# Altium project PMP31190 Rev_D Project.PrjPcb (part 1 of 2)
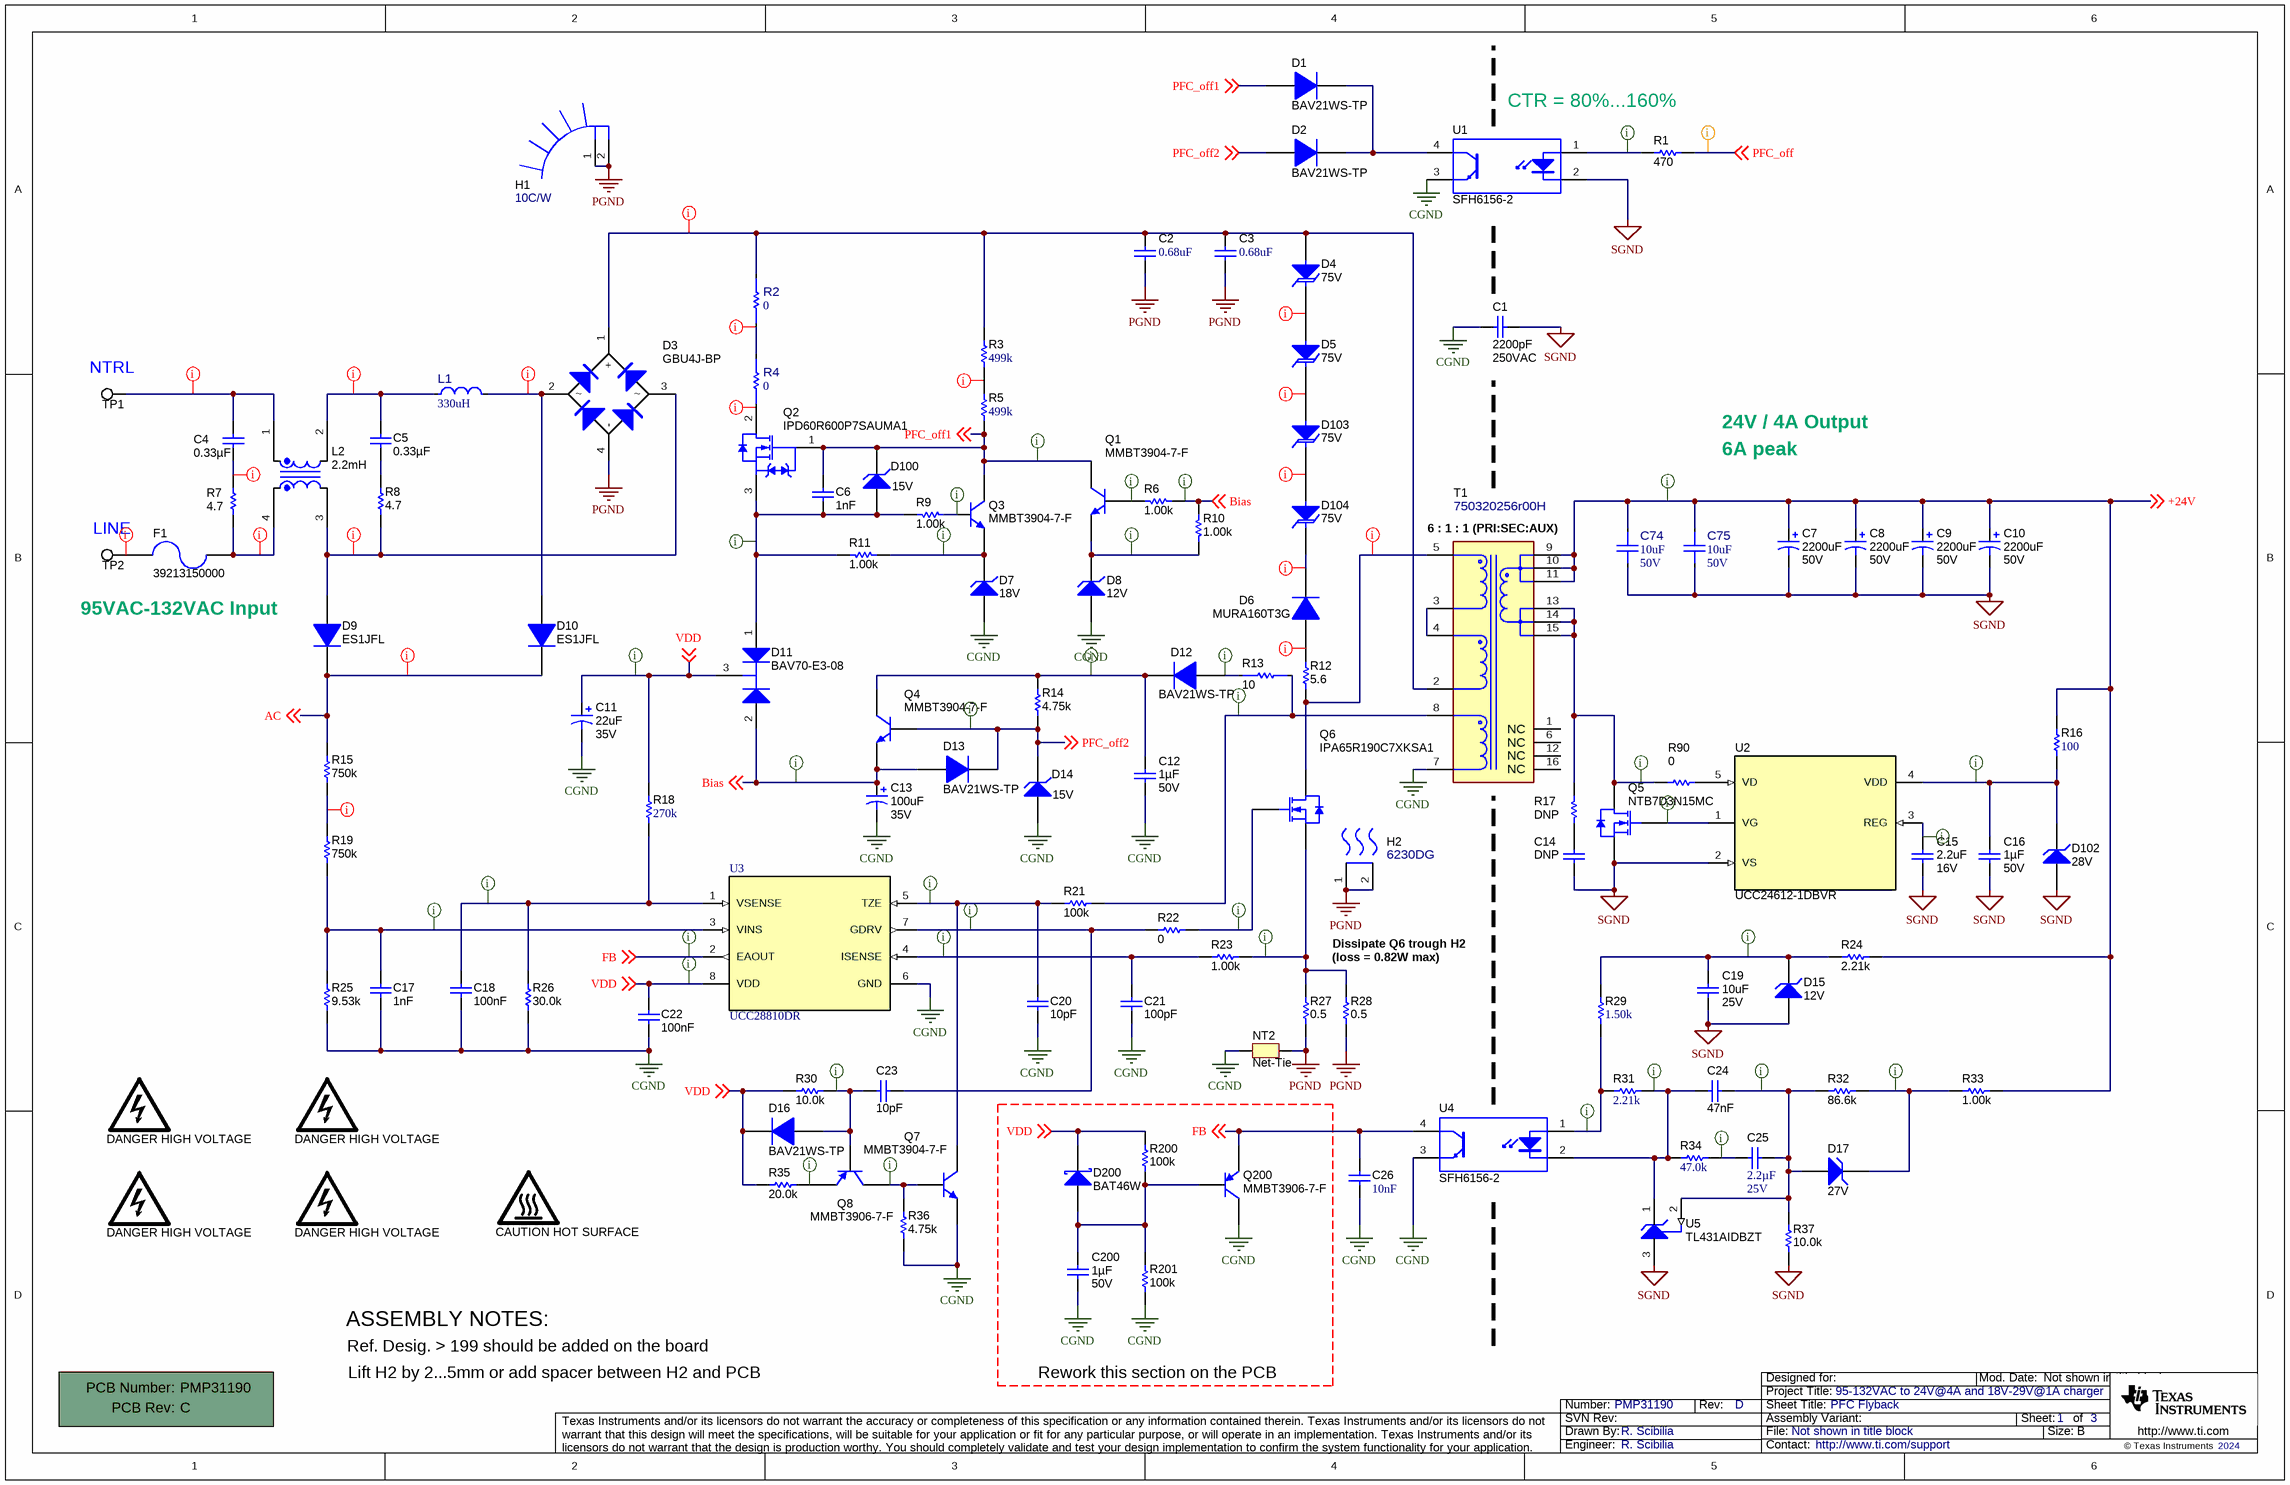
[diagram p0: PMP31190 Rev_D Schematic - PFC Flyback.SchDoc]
CopyrightYear: 2024; PCB_Layout: R Scibilia; PCB_Rev: C; PRJ_Engineer: R. Scibilia; PRJ_Number: PMP31190; PRJ_Title: 95-132VAC to 24V@4A and 18V-29V@1A charger; SCH_Rev: D; TechSupport: http://www.ti.com/support
3 sheets, 254 parts. Net scope: global (net labels, ports and power ports of the same name join across sheets).
Board file: PMP31190 Rev_C Board.PcbDoc
Sheets:
  PMP31190 Rev_D Schematic - PFC Flyback.SchDoc
  PMP31190 Rev_D Schematic - Charger.SchDoc
  PMP31190 Rev_D Schematic - LaunchPad Interface.SchDoc

## Sheet PMP31190 Rev_D Schematic - PFC Flyback.SchDoc: PFC Flyback
size 431 x 279 mm; Date: Not shown in title block; ApprovedBy: Not shown in title block; CheckedBy: Not shown in title block; Author: Not shown in title block; CompanyName: Not shown in title block; DrawnBy: R. Scibilia; Engineer: Not shown in title block; Organization: Not shown in title block; Address1: Not shown in title block; Address2: Not shown in title block; Address3: Not shown in title block; Address4: Not shown in title block; DocumentNumber: 1; Revision: Use project parameter SCH_Rev; SheetNumber: 1; SheetTotal: 3; PageSetup: Record=PageOptions¦CenterHorizontal=True¦CenterVertical=True¦PrintScale=1.00¦XCorrection=1.00¦YCorrection=1.00¦PrintKind=0¦BorderSize=5000000¦LeftOffset=0¦BottomOffset=0¦Orientation=2¦PaperLength=1000¦PaperWidth=1000¦Scale=100¦PaperSource=15¦PrintQuality=600¦MediaType=1¦DitherType=10¦PaperKind=Letter¦PrintScaleMode=1

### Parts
!PCB1  Printed Circuit Board  (value not drawn)  (mechanical)
C1  ValueDisplayed: 2200pF  VDC_V: 250VAC  [DE1_600x400x900]  (hidden comment: DE1E3RA222MA4BN01F)
C2  ValueDisplayed: 0.68uF  [B32923_16.5mm_10.5]  (hidden comment: B32923C3684M000)
C3  ValueDisplayed: 0.68uF  [B32923_16.5mm_10.5]  (hidden comment: B32923C3684M000)
C4  ValueDisplayed: 0.33µF  [WCAP-FTX2_1500x850]  (hidden comment: 890334024003)
C5  ValueDisplayed: 0.33µF  [WCAP-FTX2_1500x850]  (hidden comment: 890334024003)
C6  Cap_F: 1nF  [0603]  (hidden comment: 885012206083)
C7  VDC_V: 50V  ValueDisplayed: 2200uF  [CAPPR7.5-18x31.5]  (hidden comment: 50YXS2200MEFC18X31.5)
C8  VDC_V: 50V  ValueDisplayed: 2200uF  [CAPPR7.5-18x31.5]  (hidden comment: 50YXS2200MEFC18X31.5)
C9  VDC_V: 50V  ValueDisplayed: 2200uF  [CAPPR7.5-18x31.5]  (hidden comment: 50YXS2200MEFC18X31.5)
C10  VDC_V: 50V  ValueDisplayed: 2200uF  [CAPPR7.5-18x31.5]  (hidden comment: 50YXS2200MEFC18X31.5)
C11  VDC_V: 35V  ValueDisplayed: 22uF  [CAPSMT_62_E55]  (hidden comment: 865080542006)
C12  Cap_F: 1µF  VDC_V: 50V  [0805_HV]  (hidden comment: 885012207103)
C13  VDC_V: 35V  ValueDisplayed: 100uF  [CAPSMT_62_F80]  (hidden comment: EEE-FK1V101XP)
C14  DNP  [0805_HV]
C15  VDC_V: 16V  ValueDisplayed: 2.2uF  [0603]  (hidden comment: 885012106018)
C16  Cap_F: 1µF  VDC_V: 50V  [0805_HV]  (hidden comment: 885012207103)
C17  Cap_F: 1nF  [0603]  (hidden comment: 885012206083)
C18  Cap_F: 100nF  [0603]  (hidden comment: 885012206095)
C19  VDC_V: 25V  ValueDisplayed: 10uF  [1206_180]  (hidden comment: 885012108021)
C20  ValueDisplayed: 10pF  [0603]  (hidden comment: 885012006051)
C21  ValueDisplayed: 100pF  [0603]  (hidden comment: 885012006057)
C22  Cap_F: 100nF  [0603]  (hidden comment: 885012206095)
C23  ValueDisplayed: 10pF  [0603]  (hidden comment: 885012006051)
C24  Cap_F: 47nF  [0603]  (hidden comment: 885012206093)
C25  Cap_F: 2.2µF  VDC_V: 25V  [0805_HV]  (hidden comment: CGA4J3X7R1E225K125AB)
C26  Cap_F: 10nF  [0603]  (hidden comment: 885012206089)
C74  ValueDisplayed: 10uF  VDC_V: 50V  [FP-C3225X7R1H106K250AC_1210-MFG]  (hidden comment: C3225X7R1H106K250AC)
C75  ValueDisplayed: 10uF  VDC_V: 50V  [FP-C3225X7R1H106K250AC_1210-MFG]  (hidden comment: C3225X7R1H106K250AC)
C200  Cap_F: 1µF  VDC_V: 50V  [0805_HV]  (hidden comment: 885012207103)
D1  BAV21WS-TP  [SOD-323]
D2  BAV21WS-TP  [SOD-323]
D3  GBU4J-BP  [GBU]
D4  value 75V  [SMC]  (hidden comment: SMCJ75A)
D5  value 75V  [SMC]  (hidden comment: SMCJ75A)
D6  MURA160T3G  [SMA]
D7  value 18V  [SOD-323]  (hidden comment: MMSZ5248BS-7-F)
D8  value 12V  [SOD-323]  (hidden comment: MMSZ5242BS-7-F)
D9  ES1JFL  [MINI-SMA]
D10  ES1JFL  [MINI-SMA]
D11  BAV70-E3-08  [SOT-23L]
D12  BAV21WS-TP  [SOD-323]
D13  BAV21WS-TP  [SOD-323]
D14  value 15V  [SOD-323]  (hidden comment: MMSZ5245BS-7-F)
D15  value 12V  [SOD-323]  (hidden comment: MMSZ5242BS-7-F)
D16  BAV21WS-TP  [SOD-323]
D17  value 27V  [SOD-323]  (hidden comment: MMSZ5254BS-7-F)
D100  value 15V  [SOD-323]  (hidden comment: MMSZ5245BS-7-F)
D102  value 28V  [SOD-323]  (hidden comment: MMSZ5255BS-7-F)
D103  value 75V  [SMC]  (hidden comment: SMCJ75A)
D104  value 75V  [SMC]  (hidden comment: SMCJ75A)
D200  BAT46W  [SOD-323F]
F1  39213150000  [FUSE_392]
H1  value 10C/W  [HSINK_V6560W]  (hidden comment: V6560W)
H2  6230DG  [FP-6230DG_PTH_HTSNK-MFG]
L1  value 330uH  [FP-7447010_RADIAL-MFG]  (hidden comment: 7447060)
L2  value 2.2mH  [WE-CMB_Type_S]  (hidden comment: 744822222)
LOGO1  DANGER HIGH VOLTAGE  [IEC_HighVoltage_Small]  (no BOM)
LOGO2  DANGER HIGH VOLTAGE  [IEC_HighVoltage_Small]  (no BOM)
LOGO3  DANGER HIGH VOLTAGE  [IEC_HighVoltage_Small]  (no BOM)
LOGO4  DANGER HIGH VOLTAGE  [IEC_HighVoltage_Small]  (no BOM)
Logo5  CAUTION HOT SURFACE  [IEC_HotSurface_Small]  (no BOM)
NT2  Net-Tie  [Net-Tie_50milWide_30milLong]  (net tie, no BOM)
Q1  MMBT3904-7-F  [SOT-23]
Q2  IPD60R600P7SAUMA1  [DPAK]
Q3  MMBT3904-7-F  [SOT-23]
Q4  MMBT3904-7-F  [SOT-23]
Q5  NTB7D3N15MC  [DDPAK]
Q6  IPA65R190C7XKSA1  [TO-220FP]
Q7  MMBT3904-7-F  [SOT-23]
Q8  MMBT3906-7-F  [SOT-23]
Q200  MMBT3906-7-F  [SOT-23]
R1  ValueDisplayed: 470  [0603]  (hidden comment: RC0603FR-07470RL)
R2  value 0  [FP-RMCF1206ZT0R00_1206-MFG]  (hidden comment: RMCF1206ZT0R00)
R3  ValueDisplayed: 499k  [1206]  (hidden comment: RC1206FR-07499KL)
R4  value 0  [FP-RMCF1206ZT0R00_1206-MFG]  (hidden comment: RMCF1206ZT0R00)
R5  ValueDisplayed: 499k  [1206]  (hidden comment: RC1206FR-07499KL)
R6  ValueDisplayed: 1.00k  [0603]  (hidden comment: RC0603FR-071KL)
R7  ValueDisplayed: 4.7  [2010]  (hidden comment: CRM2010-JW-4R7ELF)
R8  ValueDisplayed: 4.7  [2010]  (hidden comment: CRM2010-JW-4R7ELF)
R9  ValueDisplayed: 1.00k  [0603]  (hidden comment: RC0603FR-071KL)
R10  ValueDisplayed: 1.00k  [0603]  (hidden comment: RC0603FR-071KL)
R11  ValueDisplayed: 1.00k  [0603]  (hidden comment: RC0603FR-071KL)
R12  ValueDisplayed: 5.6  [2512]  (hidden comment: CRCW25125R60JNEG)
R13  Res_ohm: 10  [FP-560050316012_0603-MFG]  (hidden comment: 560050316012)
R14  ValueDisplayed: 4.75k  [0603]  (hidden comment: RC0603FR-074K75L)
R15  ValueDisplayed: 750k  [1206]  (hidden comment: RC1206FR-07750KL)
R16  ValueDisplayed: 100  [0603]  (hidden comment: ESR03EZPJ101)
R17  DNP  [1206]
R18  ValueDisplayed: 270k  [0603]  (hidden comment: RC0603FR-07270KL)
R19  ValueDisplayed: 750k  [1206]  (hidden comment: RC1206FR-07750KL)
R21  ValueDisplayed: 100k  [0603]  (hidden comment: CRCW0603100KDHEAP)
R22  ValueDisplayed: 0  [0603]  (hidden comment: RMCF0603ZT0R00)
R23  ValueDisplayed: 1.00k  [0603]  (hidden comment: RC0603FR-071KL)
R24  ValueDisplayed: 2.21k  [0805_HV]  (hidden comment: ERJ-6ENF2211V)
R25  ValueDisplayed: 9.53k  [0603]  (hidden comment: RC0603FR-079K53L)
R26  ValueDisplayed: 30.0k  [0603]  (hidden comment: ERJ-3EKF3002V)
R27  ValueDisplayed: 0.5  [2512]  (hidden comment: 560050363011)
R28  ValueDisplayed: 0.5  [2512]  (hidden comment: 560050363011)
R29  ValueDisplayed: 1.50k  [0603]  (hidden comment: RC0603FR-071K5L)
R30  ValueDisplayed: 10.0k  [0603]  (hidden comment: RC0603FR-0710KL)
R31  ValueDisplayed: 2.21k  [0603]  (hidden comment: RC0603FR-072K21L)
R32  ValueDisplayed: 86.6k  [0603]  (hidden comment: RT0603DRE0786K6L)
R33  ValueDisplayed: 1.00k  [0603]  (hidden comment: RC0603FR-071KL)
R34  ValueDisplayed: 47.0k  [0603]  (hidden comment: RC0603FR-0747KL)
R35  ValueDisplayed: 20.0k  [0603]  (hidden comment: RC0603FR-0720KL)
R36  ValueDisplayed: 4.75k  [0603]  (hidden comment: RC0603FR-074K75L)
R37  ValueDisplayed: 10.0k  [0603]  (hidden comment: RC0603FR-0710KL)
R90  ValueDisplayed: 0  [0603]  (hidden comment: RMCF0603ZT0R00)
R200  ValueDisplayed: 100k  [0603]  (hidden comment: CRCW0603100KDHEAP)
R201  ValueDisplayed: 100k  [0603]  (hidden comment: CRCW0603100KDHEAP)
T1  750320256r00H  [FP-750320256r00H_TRANSFORMER_41MM9_44MM0-MFG]
TP1  5012  [Keystone5012]  (value not drawn)
TP2  5012  [Keystone5012]  (value not drawn)
U1  SFH6156-2  [SMD-4]
U2  UCC24612-1DBVR  [DBV0005A_N]
U3  UCC28810DR  [D0008A_N]
U4  SFH6156-2  [SMD-4]
U5  TL431AIDBZT  [DBZ0003A_N]

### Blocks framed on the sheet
Rework this section on the PCB: C200 D200 Q200 R200 R201

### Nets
CGND: C1.2 C11.2(-) C12.2 C13.2(-) C17.2 C18.2 C20.2 C21.2 C22.2 C26.2 C200.2 D7.2(A) D8.2(A) D14.2(A) NT2.1 Q7.2(E) Q200.3(C) R25.1 R26.1 R36.1 R201.2 T1.7 U1.3(E) U3.6(GND) U4.3(E)
PGND: C2.2 C3.2 D3.4(-) H1.1 H1.2 H2.1(MNT_1) H2.2(MNT_2) NT2.2 R27.1 R28.1
SGND: C1.1 C7.2(-) C8.2(-) C9.2(-) C10.2(-) C14.2 C15.2 C16.2 C19.2 C74.2 C75.2 D15.2(A) D102.2(A) Q5.3(S) R37.1 U1.2(K) U2.2(VS) U5.3(ANODE)
+24V: C7.1(+) C8.1(+) C9.1(+) C10.1(+) C74.1 C75.1 R16.2 R24.2 R33.1 T1.9 T1.10 T1.11 ; off-sheet +24V
AC: D9.1(K) D10.1(K) R15.2 ; off-sheet AC
Bias: C13.1(+) D11.2(K) D13.2(A) Q4.2(E) R6.1 R10.1 ; off-sheet Bias
FB: C26.1 Q200.2(E) U3.2(EAOUT) U4.4(C) ; off-sheet FB
PFC_off: R1.2 ; off-sheet PFC_off
PFC_off1: C6.1 D1.2(A) D100.1(K) Q1.3(C) Q2.1(G) Q3.3(C) R5.1 ; off-sheet PFC_off1
PFC_off2: D2.2(A) D13.1(K) D14.1(K) Q4.1(B) R14.1 ; off-sheet PFC_off2
VDD: C11.1(+) C22.1 D11.3(C) D16.1(K) D200.1(K) R18.2 R30.1 R35.1 R200.2 U3.8(VDD) ; off-sheet VDD
NetC2_1: C2.1 C3.1 D3.1(+) D4.2(A) R2.2 R3.2 T1.2
NetC4_1: C4.1 L2.1 TP1.1
NetC4_2: C4.2 R7.2
NetC5_1: C5.1 L1.1 L2.2
NetC5_2: C5.2 R8.2
NetC6_2: C6.2 D11.1(A) D100.2(A) Q2.3(S) R9.2 R11.2
NetC12_1: C12.1 D12.1(K) Q4.3(C) R14.2
NetC14_1: C14.1 R17.1
NetC15_1: C15.1 U2.3(REG)
NetC16_1: C16.1 D102.1(K) R16.1 U2.4(VDD)
NetC17_1: C17.1 R19.1 R25.2 U3.3(VINS)
NetC18_1: C18.1 R18.1 R26.2 U3.1(VSENSE)
NetC19_1: C19.1 D15.1(K) R24.1 R29.2
NetC20_1: C20.1 Q7.3(C) R21.1 U3.5(TZE)
NetC21_1: C21.1 R23.1 U3.4(ISENSE)
NetC23_1: C23.1 D16.2(A) Q8.1(B) R30.2
NetC23_2: C23.2 R22.1 U3.7(GDRV)
NetC24_1: C24.1 R31.2 R34.1 U4.2(K) U5.1(CATHODE)
NetC24_2: C24.2 C25.1 D17.2(A) R32.1 R37.2 U5.2(REF)
NetC25_2: C25.2 R34.2
NetC200_1: C200.1 D200.2(A) Q200.1(B) R200.1 R201.1
NetD1_1: D1.1(K) D2.1(K) U1.4(C)
NetD3_2: D3.2 D10.2(A) L1.2
NetD3_3: D3.3 D9.2(A) L2.3 R8.1
NetD4_1: D4.1(K) D5.2(A)
NetD5_1: D5.1(K) D103.2(A)
NetD6_1: D6.1(K) D104.1(K)
NetD6_2: D6.2(A) R12.2
NetD7_1: D7.1(K) Q3.2(E) R11.1
NetD8_1: D8.1(K) Q1.2(E) R10.2
NetD12_2: D12.2(A) R13.1
NetD17_1: D17.1(K) R32.2 R33.2
NetD103_1: D103.1(K) D104.2(A)
NetF1_1: F1.1 L2.4 R7.1
NetF1_2: F1.2 TP2.1
NetQ1_1: Q1.1(B) R6.2
NetQ2_2: Q2.2(D) R4.1
NetQ3_1: Q3.1(B) R9.1
NetQ5_1: Q5.1(G) U2.1(VG)
NetQ5_4: Q5.4(D) R17.2 R90.1 T1.13 T1.14 T1.15
NetQ6_1: Q6.1(G) R22.2
NetQ6_2: Q6.2(D) R12.1 T1.5
NetQ6_3: Q6.3(S) R23.2 R27.2 R28.2
NetQ7_1: Q7.1(B) Q8.3(C) R36.2
NetQ8_2: Q8.2(E) R35.2
NetR1_1: R1.1 U1.1(A)
NetR2_1: R2.1 R4.2
NetR3_1: R3.1 R5.2
NetR13_2: R13.2 R21.2 T1.8
NetR15_1: R15.1 R19.2
NetR29_1: R29.1 R31.1 U4.1(A)
NetR90_2: R90.2 U2.5(VD)
NetT1_3: T1.3 T1.4

Not connected (* = marked no-connect by the designer): T1 1(NC) 6(NC) 12(NC) 16(NC)

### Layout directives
rule Clearance Constraint [Clearance = 40mil]: AC, NetC2_1, NetC4_1, NetC4_2, NetC5_1, NetD3_2, NetD3_3, NetD4_1, NetD5_1, NetD6_1, NetD6_2, NetD103_1, NetF1_1, NetF1_2, NetQ2_2, NetQ6_2, NetR2_1, NetR3_1, NetR15_1
rule Clearance Constraint [Clearance = 10mil]: +24V, Bias, FB, NetC6_2, NetC12_1, NetC15_1, NetC16_1, NetC17_1, NetC18_1, NetC19_1, NetC20_1, NetC21_1, NetC23_1, NetC23_2, NetC24_1, NetC24_2, NetC25_2, NetD7_1, NetD8_1, NetD12_2, NetD17_1, NetQ1_1, NetQ3_1, NetQ5_1, NetQ5_4, NetQ6_1, NetQ6_3, NetQ7_1, NetQ8_2, NetR1_1, NetR13_2, NetR29_1, PFC_off1, PFC_off2, VDD
rule Clearance Constraint [Clearance = 9mil]: PFC_off

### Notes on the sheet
- CTR = 80%...160%
- (near TP1) NTRL
- 24V / 4A Output
- 6A peak
- LINE
- (near T1) 6 : 1 : 1 (PRI:SEC:AUX)
- 95VAC-132VAC Input
- (loss = 0.82W max)
- Dissipate Q6 trough H2
- ASSEMBLY NOTES:
- Ref. Desig. > 199 should be added on the board
- Lift H2 by 2...5mm or add spacer between H2 and PCB

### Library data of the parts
!PCB1 = PCB: Manufacturer: Any; PartNumber: PMP31190; SymbolCreator: a0412235
C1 = CMP-0077651-1: CAP, Safety, 2200 pF, 250VAC,+/- 20%, X1-Y1, D9xT4mm; Manufacturer: MuRata; Tolerance_%: 10%; SizeAreaWB_mm2: 75.6; VAC_X: 440; VAC_Y: 250; SizeArea_mm2: 42.4; AEC Qualified: N; AEC Category: Q200; Value: 2200pF; TaMax_C: 125°C; SizeZ_mm: 9.0; TempCo: B; TaMin_C: -40°C; SizeY_mm: 4.0; U/M: EA; AC_Safety: X1, Y1; SizeX_mm: 10.6; Cap_Case: 9x4x10mm
C2 C3 = CMP-0012429-3: CAP, Film, 0.68 uF, 630 V, +/- 20%, TH; Manufacturer: TDK; Polarized: N; SizeAreaWB_mm2: 356.25; Value1: Unknown; Value: 0.68uF; TaMax_C: 110°C; SizeZ_mm: 16.5; SizeX_mm: 26.5; SizeY_mm: 10.5; Value2: 630V; SizeArea_mm2: 278.25; Cap_F: 680nF; AEC Category: Q200
C4 C5 = CMP-0084596-1: CAP, Film, 0.33 µF, X2 275 VAC, +/- 10%, TH; Manufacturer: Wurth Elektronik; Cap_Case: 15x8.5mm; SizeAreaWB_mm2: 178.5; AEC Qualified: N; SizeX_mm: 15; Cap_F: 330nF; SizeY_mm: 8.5; VAC_X: 275; TaMin_C: -40°C; SizeZ_mm: 14.5; SizeArea_mm2: 127.5; Value: 0.33uF; TaMax_C: 105°C; AEC Category: Q200
C6 C17 = CMP-0064933-4: CAP, CERM, 1000 pF, 50 V,+/- 10%, X7R, 0603; Manufacturer: Wurth Elektronik; TaMin_C: -55°C; Polarized: N; SizeAreaWB_mm2: 4.68; Value1: Unknown; U/M: EA; Value: 1000pF; TaMax_C: 125°C; SizeZ_mm: 1; SizeX_mm: 1.6; SizeY_mm: 0.8; Value2: 50V; SizeArea_mm2: 1.28; AEC Category: Q200
C7-C10 = CMP-0010013-3: CAP, AL, 2200 uF, 50 V, +/- 20%, 0.018 ohm, TH; Manufacturer: Rubycon; TaMin_C: -25°C; ESR_ohm: 0.018; Polarized: Y; SizeAreaWB_mm2: 400; U/M: EA; Value: 2200uF; TaMax_C: 105°C; SizeZ_mm: 31.5; SizeX_mm: 18; AC_Derating: 0.35; SizeArea_mm2: 324; CompType: Capacitor; Cap_F: 2200µF; IRMS_A: 3.68A; AEC Category: Q200
C11 = CMP-0010802-1: CAP, AL, 22 uF, 35 V, +/- 20%, SMD; Manufacturer: Wuerth; TaMin_C: -40°C; Polarized: Y; SizeAreaWB_mm2: 53.29; Value1: Unknown; U/M: EA; Value: 22uF; TaMax_C: 85°C; SizeZ_mm: 5.2; SizeX_mm: 5.0; SizeY_mm: 5.5; Cap_Case: E55; SizeArea_mm2: 28.09; CompType: Capacitor; Cap_F: 22µF; IRMS_A: 155mA; AEC Category: Q200
C12 C16 C200 = CMP-0007696-2: CAP, CERM, 1 uF, 50 V, +/- 10%, X7R, 0805; Manufacturer: Wurth Elektronik; TaMin_C: -55°C; Polarized: N; SizeAreaWB_mm2: 6.75; Value1: Unknown; U/M: EA; Value: 1uF; TaMax_C: 125°C; SizeZ_mm: 1.45; SizeX_mm: 2; SizeY_mm: 1.25; Cap_Case: 0805; SizeArea_mm2: 2.5; AEC Category: Q200
C13 = CMP-0010800-1: CAP, AL, 100 uF, 35 V, +/- 20%, SMD; Manufacturer: Panasonic; TaMin_C: -40°C; Polarized: Y; SizeAreaWB_mm2: 73.96; Value1: Unknown; U/M: EA; Value: 100uF; TaMax_C: 85°C; SizeZ_mm: 7.7; SizeX_mm: 6.6; Cap_Case: F80; SizeArea_mm2: 43.56; CompType: Capacitor; Cap_F: 100µF; IRMS_A: 280mA; AEC Category: Q200
C14 = CMP-0007872-2: Manufacturer: TDK; TaMin_C: -55°C; Polarized: N; TempCo: X7R; SizeAreaWB_mm2: 6.75; Value1: Unknown; U/M: EA; TaMax_C: 125°C; Tolerance_%: 10%; SizeZ_mm: 1.45; SizeX_mm: 2; SizeY_mm: 1.25; Cap_Case: 0805; Value2: 50V; SizeArea_mm2: 2.5; AEC Category: Q200
C15 = CMP-0006825-5: CAP, CERM, 2.2 uF, 16 V, +/- 20%, X5R, 0603; Manufacturer: Wurth Elektronik; TaMin_C: -55°C; Polarized: N; SizeAreaWB_mm2: 4.68; Value1: Unknown; U/M: EA; Value: 2.2uF; TaMax_C: 85°C; SizeZ_mm: 1; SizeX_mm: 1.6; SizeY_mm: 0.8; SizeArea_mm2: 1.28; Cap_F: 2.2µF; AEC Category: Q200
C18 C22 = CMP-0006837-3: CAP, CERM, 0.1 uF, 50 V, +/- 10%, X7R, 0603; Manufacturer: Wurth Elektronik; TaMin_C: -55°C; Polarized: N; SizeAreaWB_mm2: 4.68; Value1: Unknown; U/M: EA; Value: 0.1uF; TaMax_C: 125°C; SizeZ_mm: 1; SizeX_mm: 1.6; SizeY_mm: 0.8; Value2: 50V; SizeArea_mm2: 1.28; AEC Category: Q200
C19 = CMP-0008950-2: CAP, CERM, 10 uF, 25 V, +/- 10%, X5R, 1206; Manufacturer: Wuerth; TaMin_C: -55°C; ESR_ohm: 4m; Polarized: N; SizeAreaWB_mm2: 10.92; Value1: 0.004 ohm; U/M: EA; Value: 10uF; TaMax_C: 85°C; SizeZ_mm: 1.8; SizeX_mm: 3.2; SizeY_mm: 1.6; Cap_Case: 1206; SizeArea_mm2: 5.12; Cap_F: 10µF; AEC Category: Q200
C20 C23 = CMP-0006761-4: CAP, CERM, 10 pF, 50 V, +/- 5%, C0G/NP0, 0603; Manufacturer: Wuerth; TaMin_C: -55°C; ESR_ohm: 0.403; Polarized: N; SizeAreaWB_mm2: 4.68; Value1: 0.403 ohm; U/M: EA; Value: 10pF; TaMax_C: 125°C; SizeZ_mm: 1; SizeX_mm: 1.6; SizeY_mm: 0.8; Value2: 50V; SizeArea_mm2: 1.28; AEC Category: Q200
C21 = CMP-0006822-4: CAP, CERM, 100 pF, 50 V, +/- 5%, C0G/NP0, 0603; Manufacturer: Wurth Elektronik; TaMin_C: -55°C; Polarized: N; SizeAreaWB_mm2: 4.68; Value1: Unknown; U/M: EA; Value: 100pF; TaMax_C: 125°C; SizeZ_mm: 1; SizeX_mm: 1.6; SizeY_mm: 0.8; Value2: 50V; SizeArea_mm2: 1.28; AEC Category: Q200
C24 = CMP-0085252-1: CAP, CERM, 0.047 µF, 50 V,+/- 5%, X7R, 0603; Manufacturer: Wuerth; VDC_V: 50V; TaMax_C: 125°C; Value: 0.047uF; SizeX_mm: 1.6; SizeArea_mm2: 1.28; AEC Category: Q200; SizeY_mm: 0.8; Polarized: N; SizeAreaWB_mm2: 4.68; U/M: EA; TaMin_C: -55°C; SizeZ_mm: 1
C25 = CMP-0007975-2: CAP, CERM, 2.2 uF, 25 V, +/- 10%, X7R, AEC-Q200 Grade 1, 0805; Manufacturer: TDK; TaMin_C: -55°C; Polarized: N; SizeAreaWB_mm2: 6.75; Value1: Unknown; U/M: EA; Value: 2.2uF; TaMax_C: 125°C; SizeZ_mm: 1.45; SizeX_mm: 2; SizeY_mm: 1.25; Cap_Case: 0805; SizeArea_mm2: 2.5; AEC Qualified: Y; AEC Grade: 1; AEC Category: Q200
C26 = CMP-0750039-1: CAP, CERM, 0.01 µF, 50 V,+/- 10%, X7R, 0603; Manufacturer: Wurth Elektronik; Polarized: N; AEC Category: Q200; TaMax_C: 125°C; SizeAreaWB_mm2: 4.68; Value: 0.01uF; SizeArea_mm2: 1.28; SizeY_mm: 0.8; SizeZ_mm: 1; ValueDisplayed: 0.01µF; SizeX_mm: 1.6; VDC_V: 50V; U/M: EA; TaMin_C: -55°C
C74 C75 = CMP-0126787-1: Multilayer Ceramic Capacitors 10uF ±10% 50V X7R SMD 1210; Manufacturer: TDK; AEC Qualified: No; Cap_F: 10µF; SizeZ_mm: 2.8mm; TempCo: 0.15; Tolerance_%: 0.1%; Value: 10µF
D1 D2 D12 D13 D16 = CMP-0077069-2: Diode, Standard Recovery Rectifier, 250 V, 0.2 A, SOD-323; Manufacturer: Micro Commercial Components; TJmax_C: 150°C; AEC Category: Q101; Green_Lifecycle: Not Set; Value: 250V; Vf_V: 1.25V; SizeZ_mm: 1.0; Value1: 0.2A; SizeX_mm: 2.7; SizeAreaWB_mm2: 8.695; SizeArea_mm2: 3.645; AEC Qualified: N; Io_A: 200mA; SizeY_mm: 1.35; Green_REACh: Incomplete
D3 = CMP-0029241-1: Diode, P-N-Bridge, 600 V, 4 A, TH; Manufacturer: Micro Commercial Components; Io_A: 4A; Green_Lifecycle: Not Set; SizeAreaWB_mm2: 130.5915; Vr_V: 600V; Green_REACh: Incomplete; TJmax_C: 150°C; U/M: EA; Value: 600V; SizeZ_mm: 21.55; SizeX_mm: 22.05; SizeY_mm: 3.43; Vf_V: 1V; SizeArea_mm2: 75.6315; AEC Category: Q101; RJC_CperW: 2.2
D4 D5 D103 D104 = CMP-0005722-3: Diode, TVS, Uni, 75 V, SMC; Manufacturer: Fairchild Semiconductor; SizeX_mm: 8.13; AEC Category: Q101; SizeY_mm: 6.22; SizeZ_mm: 2.6; Ppk: 1.5kW; SizeAreaWB_mm2: 83.2686; Value1: 1500W; SizeArea_mm2: 50.5686
D6 = CMP-0029033-2: Diode, Ultrafast, 600 V, 1 A, AEC-Q101, SMA; Manufacturer: ON Semiconductor; AEC Category: Q101; SizeX_mm: 5.59; Io_A: 1A; Green_Lifecycle: Active; Value2: 1.05V; SizeArea_mm2: 16.3228; SizeZ_mm: 2.87; TJmax_C: 175°C; Value: 600V; AEC Qualified: Y; SizeAreaWB_mm2: 37.3428; SizeY_mm: 2.92; Green_REACh: Passed
D7 = CMP-0005835-4: Diode, Zener, 18 V, 200 mW, SOD-323; Manufacturer: Diodes Inc.; Value1: 0.2W; SizeArea_mm2: 3.645; AEC Category: Q101; Power_W: 200mW; SizeAreaWB_mm2: 8.695; SizeY_mm: 1.35; RJA_CperW: 350; SizeZ_mm: 1; SizeX_mm: 2.7
D8 D15 = CMP-0005831-4: Diode, Zener, 12 V, 200 mW, SOD-323; Manufacturer: Diodes Inc.; Power_W: 200mW; SizeZ_mm: 1; SizeX_mm: 2.7; SizeAreaWB_mm2: 8.695; Value1: 0.2W; RJA_CperW: 350; AEC Category: Q101; SizeArea_mm2: 3.645; SizeY_mm: 1.35
D9 D10 = CMP-0076945-2: Diode, P-N, 600 V, 1 A, MINI-SMA; Manufacturer: Taiwan semiconductor corporation; Green_Lifecycle: Not Set; Vr_V: 600V; Vf_V: 1.1V; SizeZ_mm: 1.7; SizeX_mm: 3.7; Value: 600V; SizeAreaWB_mm2: 12.22; AEC Qualified: N; SizeArea_mm2: 5.92; Io_A: 1A; TJmax_C: 150°C; AEC Category: Q101; SizeY_mm: 1.6; Green_REACh: Incomplete
D11 = CMP-0077061-2: Diode, Switching, 70 V, 0.25 A, AEC-Q101, SOT-23; Manufacturer: Vishay-Semiconductor; SizeZ_mm: 1.1; AEC Qualified: Y; Value: 70V; SizeY_mm: 3.0; Value2: 1.25V; SizeArea_mm2: 7.5; AEC Category: Q101; SizeAreaWB_mm2: 14.0; Value1: 0.25A; Io_A: 250mA; SizeX_mm: 2.5; Green_REACh: Incomplete; TJmax_C: 150°C; Green_Lifecycle: Not Set
D14 D100 = CMP-0005833-4: Diode, Zener, 15 V, 200 mW, SOD-323; Manufacturer: Diodes Inc.; SizeY_mm: 1.35; RJA_CperW: 350; SizeX_mm: 2.7; AEC Category: Q101; SizeAreaWB_mm2: 8.695; SizeZ_mm: 1; Power_W: 200mW; SizeArea_mm2: 3.645; Value1: 0.2W
D17 = CMP-0005839-4: Diode, Zener, 27 V, 200 mW, SOD-323; Manufacturer: Diodes Inc.; SizeX_mm: 2.7; AEC Category: Q101; Power_W: 200mW; SizeZ_mm: 1; Value1: 0.2W; SizeArea_mm2: 3.645; RJA_CperW: 350; SizeAreaWB_mm2: 8.695; SizeY_mm: 1.35
D102 = CMP-0005839-4: Diode, Zener, 28 V, 200 mW, SOD-323; Manufacturer: Diodes Inc.; SizeX_mm: 2.7; AEC Category: Q101; Power_W: 200mW; SizeZ_mm: 1; Value1: 0.2W; SizeArea_mm2: 3.645; RJA_CperW: 350; SizeAreaWB_mm2: 8.695; SizeY_mm: 1.35
D200 = CMP-0076946-2: Diode, Schottky, 100 V, 0.25 A, SOD-323F; Manufacturer: Nexperia; PartNumber: BAT46WJ,115; SizeAreaWB_mm2: 7.875; Value2: 0.85V; SizeX_mm: 2.5; Green_REACh: Incomplete; SizeArea_mm2: 3.125; Vf_V: 850mV; Green_Lifecycle: Not Set; Vr_V: 100V; TJmax_C: 150°C; Value1: 0.25A; Io_A: 250mA; SizeZ_mm: 0.8; Value: 100V; AEC Category: Q101; SizeY_mm: 1.25
F1 = CMP-0003561-2: Fuse, 3.15 A, 250VAC/VDC, TH; Manufacturer: Littelfuse; Irating_A: 3.15A; VAC_V: 250V
H1 = CMP-0086362-1: Heat Sink TO-220; Manufacturer: Assman WSW
H2 = CMP-0095825-2: Heat Sink Passive TO-220 Straight Copper 12.5°C/W Matte Tin; PartNumber: 6230DG (COPPER); Manufacturer: Aavid; SizeZ_mm: 29.97mm; AEC Qualified: No
L1 = CMP-0091284-1: 300µH Unshielded Toroidal Inductor 2.5A 150mOhm Max Radial, Vertical (Open); Manufacturer: Wurth Electronics; SizeZ_mm: 21mm; AEC Qualified: No; TaMin_C: -40°C; Tolerance_%: 20%; Material: Iron Powder; Test Frequency: 10kHz; TaMax_C: +65°C; Ind_H: 330µH; DCR_ohm: 0.150
L2 = CMP-0013143-1: Coupled inductor, 2.2 mH,  A, 0.07 ohm, TH; Manufacturer: Wurth Elektronik; DCR_ohm: 70m
LOGO1-LOGO4 = CMP-0074835-1: IEC 61010-1 High Voltage Warning; SymbolCreator: a0412235
Logo5 = CMP-0074837-2: IEC 61010-1 Hot Surface Warning; Manufacturer: Texas Instruments; CompType: IC; AEC Category: Q200; SymbolCreator: a0412235
NT2 = CMP-0078142-5: Single point connection between nets.
Q1 Q3 Q4 Q7 = CMP-0000387-2: Transistor, NPN, 40 V, 0.2 A, SOT-23; Manufacturer: Diodes Inc.; TaMax_C: 150°C; Value2: 400; Value1: 0.2 A; Vcesat1_V: 200mV; SizeX_mm: 2.5; SizeY_mm: 3; TaMin_C: -55°C; IcRated_A: 200mA; CompType: BJT; SizeZ_mm: 1.1; Value: 40 V; SizeArea_mm2: 7.5; NPN: 1; Vceo_V: 40V; PNP: 0; AEC Category: Q101; SizeAreaWB_mm2: 14; U/M: EA
Q2 = CMP-0081319-2: MOSFET, N-CH, 600 V, 6 A, DPAK; Alternate Manufacturer: None; Manufacturer: Infineon Technologies; ChMode: Enhancement; IdsMax_A: 6A; Value2: 9 nC; VdsMax_V: 600V; AEC Qualified: N; Vgs_V: 20V; QgTyp_nC: 9; Value1: ? ohm; SizeX_mm: 9.91; SizeZ_mm: 2.29; SizeY_mm: 6.54; Value: 600V; SizeAreaWB_mm2: 101.7114; SizeArea_mm2: 64.8114; AEC Category: Q101
Q5 = CMP-0001215-2: MOSFET, N-CH, 150 V, 101 A, DDPAK; Alternate Manufacturer: None; Manufacturer: On semi; SizeZ_mm: 4.445; ChType: N; Value2: 53 nC; VdsMax_V: 150V; SizeX_mm: 15.245; SizeY_mm: 10.16; Vgs_V: 20V; QgTyp_nC: 96; SizeArea_mm2: 154.8892; AEC Category: Q101; IdsMax_A: 101A; SizeAreaWB_mm2: 209.6992; U/M: EA
Q6 = CMP-0067578-2: MOSFET, N-CH, 650 V, 8 A, TO-220FP; Alternate Manufacturer: None; Manufacturer: Infineon Technologies; QgTyp_nC: 24.0; SizeAreaWB_mm2: 79.3; Vgs_V: 20V; Value1: ? ohm; VdsMax_V: 700V; U/M: EA; IdsMax_A: 9A; SizeZ_mm: 20.0; SizeX_mm: 10.2; SizeY_mm: 4.5; Value2: 23 nC; SizeArea_mm2: 45.9; ChType: N; AEC Category: Q101
Q8 Q200 = CMP-0000326-2: Transistor, PNP, 40 V, 0.2 A, SOT-23; Manufacturer: Diodes Inc.; TaMax_C: 150°C; Value2: 400; Value1: 0.2 A; Vcesat1_V: 250mV; SizeX_mm: 2.5; SizeY_mm: 3; TaMin_C: -55°C; IcRated_A: 200mA; CompType: BJT; SizeZ_mm: 1.1; Value: 40 V; SizeArea_mm2: 7.5; NPN: 0; Vceo_V: 40V; PNP: 1; AEC Category: Q101; SizeAreaWB_mm2: 14; U/M: EA
R1 = CMP-0023129-5: RES, 470, 1%, 0.1 W, 0603; Manufacturer: Yageo; Power_W: 100mW; TempCo: 100 ppm/C; Value_Code: 470R; Value: 470; SizeX_mm: 1.6; SizeY_mm: 0.8; SizeZ_mm: 1; Value2: 0.1W; SizeArea_mm2: 1.28; AEC Qualified: N; VDC_V: 75V; AEC Category: Q200; SizeAreaWB_mm2: 4.68
R2 R4 = CMP-0093609-1: 0Ω ±0 0.25W 1206 Thick Film Chip Resistor AEC-Q200 compliant; Manufacturer: Stackpole Electronics; AEC Qualified: Yes; VDC_V: 200V; AEC Grade: Grade 0; Power_W: 250mW; SizeZ_mm: 0.7mm
R3 R5 = CMP-0018325-2: RES, 499 k, 1%, 0.25 W, 1206; Manufacturer: Yageo America; Power_W: 250mW; TempCo: 100 ppm/C; U/M: EA; Value: 499k; EIA_Code: E96; SizeX_mm: 3.2; SizeY_mm: 1.6; SizeZ_mm: 1.35; Value2: 0.25W; SizeArea_mm2: 5.12; VDC_V: 200V; AEC Category: Q200
R6 R9-R11 R23 R33 = CMP-0022895-5: RES, 1.00 k, 1%, 0.1 W, 0603; Manufacturer: Yageo; Power_W: 100mW; TempCo: 100 ppm/C; Value_Code: 1k00; Value: 1.00k; EIA_Code: E96; Res_ohm: 1k; SizeX_mm: 1.6; SizeY_mm: 0.8; SizeZ_mm: 1; Value2: 0.1W; SizeArea_mm2: 1.28; AEC Qualified: N; VDC_V: 75V; AEC Category: Q200; SizeAreaWB_mm2: 4.68
R7 R8 = CMP-0016196-2: RES, 4.7, 5%, 1 W, 2010; Manufacturer: Bourns; Power_W: 1W; TempCo: 100 ppm/C; Value_Code: 4R70; U/M: EA; Value: 4.7; EIA_Code: E24; SizeX_mm: 5; SizeY_mm: 2.5; SizeZ_mm: 1.66; SizeArea_mm2: 12.5; VDC_V: 2V; AEC Category: Q200
R12 = CMP-0015987-3: RES, 5.6, 5%, 1 W, AEC-Q200 Grade 0, 2512; Manufacturer: Vishay-Dale; Power_W: 1W; TempCo: 200 ppm/C; Value_Code: 5R60; Value: 5.6; EIA_Code: E24; SizeX_mm: 6.3; SizeY_mm: 3.2; SizeZ_mm: 0.71; SizeArea_mm2: 20.16; AEC Qualified: Y; VDC_V: 500V; AEC Grade: 0; AEC Category: Q200
R13 = CMP-0087986-1: WRIS-KSKE Thick Film Resistors; Manufacturer: Wurth Electronics; Tolerance_%: 1%; AEC Qualified: No; TempCo: 100ppm/°C; Symbol Name: SYM-560050316012; Power_W: 250mW; SizeZ_mm: 0.55mm; VDC_V: 1.5811V
R14 R36 = CMP-0023152-5: RES, 4.75 k, 1%, 0.1 W, 0603; Manufacturer: Yageo; Power_W: 100mW; TempCo: 100 ppm/C; Value_Code: 4k75; Value: 4.75k; EIA_Code: E96; SizeX_mm: 1.6; SizeY_mm: 0.8; SizeZ_mm: 1; Value2: 0.1W; SizeArea_mm2: 1.28; AEC Qualified: N; VDC_V: 75V; AEC Category: Q200; SizeAreaWB_mm2: 4.68
R15 R19 = CMP-0018469-2: RES, 750 k, 1%, 0.25 W, 1206; Manufacturer: Yageo America; Power_W: 250mW; TempCo: 100 ppm/C; U/M: EA; Value: 750k; EIA_Code: E96; SizeX_mm: 3.2; SizeY_mm: 1.6; SizeZ_mm: 1.35; Value2: 0.25W; SizeArea_mm2: 5.12; VDC_V: 200V; AEC Category: Q200
R16 = CMP-0025882-3: RES, 100, 5%, 0.25 W, AEC-Q200 Grade 0, 0603; Manufacturer: Rohm; Power_W: 250mW; TempCo: 200 ppm/C; Value_Code: 100R; U/M: EA; Value: 100; EIA_Code: E24; SizeX_mm: 1.6; SizeY_mm: 0.8; SizeZ_mm: 1; Value2: 0.25W; SizeArea_mm2: 1.28; AEC Qualified: Y; VDC_V: 150V; AEC Grade: 0; AEC Category: Q200
R17 = CMP-0017631-3: Manufacturer: Panasonic; Power_W: 250mW; TempCo: 100 ppm/C; Value1: 1%; EIA_Code: E96; SizeX_mm: 3.2; SizeY_mm: 1.6; SizeZ_mm: 1.35; Value2: 0.25W; SizeArea_mm2: 5.12; AEC Qualified: Y; VDC_V: 200V; AEC Category: Q200; AEC Grade: 0; SizeAreaWB_mm2: 10.92
R18 = CMP-0022961-4: RES, 270 k, 1%, 0.1 W, 0603; Manufacturer: Yageo; Power_W: 100mW; TempCo: 100 ppm/C; Value: 270k; SizeX_mm: 1.6; SizeY_mm: 0.8; SizeZ_mm: 1; Value2: 0.1W; SizeArea_mm2: 1.28; AEC Qualified: N; VDC_V: 75V; AEC Category: Q200; SizeAreaWB_mm2: 4.68
R21 R200 R201 = CMP-0086261-1: RES, 100 k, 0.5%, 0.1 W, AEC-Q200 Grade 0, 0603; Manufacturer: Vishay-Dale; EIA_Code: E192; SizeZ_mm: 1; Power_W: 100mW; Value2: 0.1W; Value: 100k; SizeAreaWB_mm2: 4.68; AEC Qualified: Y; TempCo: 50 ppm/C; SizeArea_mm2: 1.28; AEC Category: Q200; SizeX_mm: 1.6; SizeY_mm: 0.8; AEC Grade: 0
R22 R90 = CMP-0023343-3: RES, 0, 1%, 0.1 W, AEC-Q200 Grade 0, 0603; Manufacturer: Stackpole Electronics Inc; Power_W: 100mW; TempCo: ppm/C; U/M: EA; Value: 0; SizeX_mm: 1.6; SizeY_mm: 0.8; SizeZ_mm: 1; Value2: 0.1W; SizeArea_mm2: 1.28; AEC Qualified: Y; AEC Category: Q200
R24 = CMP-0021627-3: RES, 2.21 k, 1%, 0.125 W, AEC-Q200 Grade 0, 0805; Manufacturer: Panasonic; Power_W: 125mW; TempCo: 100 ppm/C; Value_Code: 2k21; Value: 2.21k; EIA_Code: E96; SizeX_mm: 2; SizeY_mm: 1.25; SizeZ_mm: 1.45; Value2: 0.125W; SizeArea_mm2: 2.5; AEC Qualified: Y; AEC Category: Q200; AEC Grade: 0; SizeAreaWB_mm2: 6.75
R25 = CMP-0023335-5: RES, 9.53 k, 1%, 0.1 W, 0603; Manufacturer: Yageo; Power_W: 100mW; TempCo: 100 ppm/C; Value_Code: 9k53; Value: 9.53k; EIA_Code: E96; SizeX_mm: 1.6; SizeY_mm: 0.8; SizeZ_mm: 1; Value2: 0.1W; SizeArea_mm2: 1.28; AEC Qualified: N; VDC_V: 75V; AEC Category: Q200; SizeAreaWB_mm2: 4.68
R26 = CMP-0022695-3: RES, 30.0 k, 1%, 0.1 W, AEC-Q200 Grade 0, 0603; Manufacturer: Panasonic; Power_W: 100mW; TempCo: 100 ppm/C; Value_Code: 30k0; U/M: EA; Value: 30.0k; Res_ohm: 30k; SizeX_mm: 1.6; SizeY_mm: 0.8; SizeZ_mm: 1; Value2: 0.1W; SizeArea_mm2: 1.28; AEC Qualified: Y; VDC_V: 75V; AEC Grade: 0; AEC Category: Q200
R27 R28 = CMP-0015769-1: RES, 0.5, 1%, 1 W, 2512; Manufacturer: Wuerth; Power_W: 1W; TempCo: 200 ppm/C; Value_Code: R500; U/M: EA; Value: 0.5; SizeX_mm: 6.3; SizeY_mm: 3.2; SizeZ_mm: 0.71; SizeArea_mm2: 20.16; AEC Category: Q200
R29 = CMP-0022883-5: RES, 1.50 k, 1%, 0.1 W, 0603; Manufacturer: Yageo; Power_W: 100mW; TempCo: 100 ppm/C; Value_Code: 1k50; Value: 1.50k; EIA_Code: E96; Res_ohm: 1.5k; SizeX_mm: 1.6; SizeY_mm: 0.8; SizeZ_mm: 1; Value2: 0.1W; SizeArea_mm2: 1.28; AEC Qualified: N; VDC_V: 75V; AEC Category: Q200; SizeAreaWB_mm2: 4.68
R30 R37 = CMP-0022746-5: RES, 10.0 k, 1%, 0.1 W, 0603; Manufacturer: Yageo; Power_W: 100mW; TempCo: 100 ppm/C; Value_Code: 10k0; Value: 10.0k; EIA_Code: E96; Res_ohm: 10k; SizeX_mm: 1.6; SizeY_mm: 0.8; SizeZ_mm: 1; Value2: 0.1W; SizeArea_mm2: 1.28; AEC Qualified: N; VDC_V: 75V; AEC Category: Q200; SizeAreaWB_mm2: 4.68
R31 = CMP-0022984-5: RES, 2.21 k, 1%, 0.1 W, 0603; Manufacturer: Yageo; Power_W: 100mW; TempCo: 100 ppm/C; Value_Code: 2k21; Value: 2.21k; EIA_Code: E96; SizeX_mm: 1.6; SizeY_mm: 0.8; SizeZ_mm: 1; Value2: 0.1W; SizeArea_mm2: 1.28; AEC Qualified: N; VDC_V: 75V; AEC Category: Q200; SizeAreaWB_mm2: 4.68
R32 = CMP-0025613-3: RES, 86.6 k, 0.5%, 0.1 W, 0603; Manufacturer: Yageo America; Power_W: 100mW; TempCo: 50 ppm/C; Value_Code: 86k6; U/M: EA; Value: 86.6k; EIA_Code: E192; SizeX_mm: 1.6; SizeY_mm: 0.8; SizeZ_mm: 1; Value2: 0.1W; SizeArea_mm2: 1.28; VDC_V: 75V; AEC Category: Q200
R34 = CMP-0023133-5: RES, 47.0 k, 1%, 0.1 W, 0603; Manufacturer: Yageo; Power_W: 100mW; TempCo: 100 ppm/C; Value_Code: 47k0; Value: 47.0k; Res_ohm: 47k; SizeX_mm: 1.6; SizeY_mm: 0.8; SizeZ_mm: 1; Value2: 0.1W; SizeArea_mm2: 1.28; AEC Qualified: N; VDC_V: 75V; AEC Category: Q200; SizeAreaWB_mm2: 4.68
R35 = CMP-0022906-5: RES, 20.0 k, 1%, 0.1 W, 0603; Manufacturer: Yageo; Power_W: 100mW; TempCo: 100 ppm/C; Value_Code: 20k0; Value: 20.0k; EIA_Code: E96; Res_ohm: 20k; SizeX_mm: 1.6; SizeY_mm: 0.8; SizeZ_mm: 1; Value2: 0.1W; SizeArea_mm2: 1.28; AEC Qualified: N; VDC_V: 75V; AEC Category: Q200; SizeAreaWB_mm2: 4.68
T1 = CMP-0096640-1: Transformer 6:1 3000VAC 250uH 41.90x44.00x31.75mm; Manufacturer: Wurth Electronics; Rsec1_ohm: 0.14; Ind_H: 250µH; DCR_ohm: 85m; Frequency_Fixed: 100kHz; AEC Qualified: No; Voltage_Isolation_Vrms: 3kV
TP1 TP2 = CMP-0055149-2: Test Point, Multipurpose, White, TH; Manufacturer: Keystone Electronics; ContactFinish: Silver; CT: TRUE; CNHeader: FALSE; Green_Lifecycle: Active; Green_REACh: Passed
U1 U4 = CMP-0006172-3: Optocoupler, 5.3 kV, 63-125% CTR, SMT; Manufacturer: Vishay-Semiconductor; CTR (Max): 125%; CTR (Min): 63%; Voltage_Isolation_Vrms: 5.3kV
U2 = CMP-0013050-3: High-Frequency Multi-Mode Synchronous Rectifier Controller, DBV0005A (SOT-23-5); Manufacturer: Texas Instruments; Alternate PartNumber: UCC24612-1DBVT; SizeX_mm: 2.8; SizeY_mm: 2.9; CompType: IC; SizeZ_mm: 1.45; SizeArea_mm2: 8.12; SizeAreaWB_mm2: 14.82; AEC Category: Q200; AEC Qualified: N
U3 = CMP-0029884-1: LED Lighting Power Controller, -40 to +105 degC, 8-pin SOIC (D), Green (RoHS & no Sb/Br); Manufacturer: Texas Instruments; Rating: Catalog; Frequency(Max)(kHz): 200
U5 = CMP-0033091-1: Adjustable Precision Shunt Regulator, 34 ppm / degC, 100 mA, -40 to 85 degC, 3-pin SOT-23 (DBZ), Green (RoHS & no Sb/Br); Manufacturer: Texas Instruments; Temp Coeff(Typ)(ppm/ degree C): 34; SubFamily: Shunt Voltage Reference; Min Iz for Regulation(uA): 600; Iout/Iz(Max)(mA): 100; VO Adj(Min)(V): 2.495; Rating: Catalog; VO Adj(Max)(V): 36; Temp Coeff(Max)(ppm/ degree C): 92; Initial Accuracy @ 25/deg C(%): 1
